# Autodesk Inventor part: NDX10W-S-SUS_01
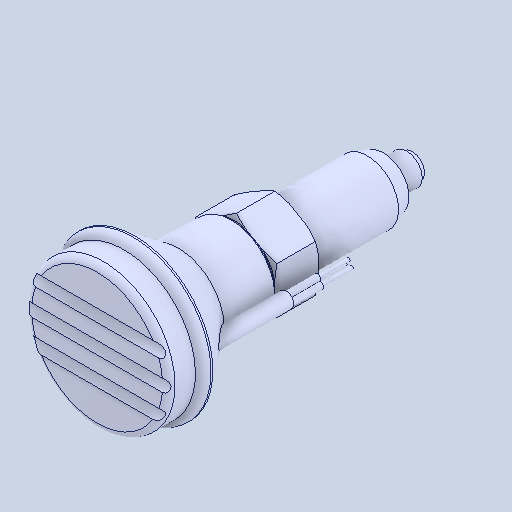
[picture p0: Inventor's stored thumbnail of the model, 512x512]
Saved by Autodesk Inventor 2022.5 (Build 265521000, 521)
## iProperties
Created: 2024-05
Part Number: NDX10W-S-SUS_01
Material: 一般
Document SubType Name: Modeling
Designer: ImaoCorp
Density: 1 g/cm^3
Appearance: 既定
Author: ImaoCorp
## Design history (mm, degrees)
feature "NDX10W-S-SUS_01"
node "ソリッド1"
